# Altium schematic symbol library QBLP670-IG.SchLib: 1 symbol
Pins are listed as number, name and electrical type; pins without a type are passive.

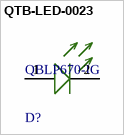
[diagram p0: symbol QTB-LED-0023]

## QTB-LED-0023
designator D?, comment QBLP670-IG
LED GREEN CLEAR 2PLCC SMD; Manufacturer: QT Brightek (QTB); Luminous Intensity: 900mcd; Test Current: 20mA; Lens Color: Colorless; Lens Style: Oval with Flat Top; Forward Voltage: 3.1V; Wavelength - Dominant: 525nm; Viewing Angle: 120°
footprint QBLP670-IG
pins: 1 ANODE (+), 2 CATHODE (-)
